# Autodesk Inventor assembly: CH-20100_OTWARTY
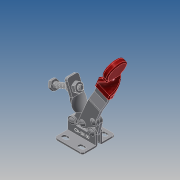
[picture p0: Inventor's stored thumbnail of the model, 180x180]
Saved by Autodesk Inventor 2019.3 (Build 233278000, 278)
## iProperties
Company: Î¢ÈíÖÐ¹ú
Created: 2012-09
Part Number: CH-20100_OTWARTY
Material: Ogólny
Description: STEP AP203
Document SubType Name: Assembly
Designer: CADENGINEERING4
Sending System: SolidWorks 2010
Preprocessor: SwSTEP 2.0
Title: CH-20100.STEP
Author: Î¢ÈíÓÃ»§
Revision Number: ÈÎºÎ
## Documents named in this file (10)
- E:\STRONA\Horizontal toggle clamp\CH-20100\CH-20100_OTWARTY.iam
- E:\STRONA\Horizontal toggle clamp\CH-20100\CH-20100-03 HANDLE.ipt
- E:\STRONA\Horizontal toggle clamp\CH-20100\CH-20100-08.ipt
- E:\STRONA\Horizontal toggle clamp\CH-20100\CH-20100-06.ipt
- E:\STRONA\Horizontal toggle clamp\CH-20100\CH-SA-042507 SPINDLE SUPPLIED.ipt
- E:\STRONA\Horizontal toggle clamp\CH-20100\CH-20100-02 SOLID BAR.ipt
- E:\STRONA\Horizontal toggle clamp\CH-20100\CH-20100-05.ipt
- E:\STRONA\Horizontal toggle clamp\CH-20100\M4 Nut.ipt
- E:\STRONA\Horizontal toggle clamp\CH-20100\CH-20100-01 FLANGED BASE.ipt
- E:\STRONA\Horizontal toggle clamp\CH-20100\CH-20100-04 CONNECTING-PLATE.ipt
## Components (12 placed, 12 different names)
1. CH-20100-03 HANDLE_1 — Zestawiające:1, Zestawiające:2, Zestawiające:3, Zestawiające:23, Zestawiające:24, Zestawiające:25, Zestawiające:26, Zestawiające:27, Przejściowe:1
2. CH-20100-08_2 — Zestawiające:22, Zestawiające:27
3. CH-20100-06_3 — Zestawiające:11, Zestawiające:12
4. CH-SA-042507 SPINDLE SUPPLIED_4 — Równoległe:1, Zestawiające:4, Zestawiające:5, Zestawiające:8
5. CH-20100-02 SOLID BAR_5 — Zestawiające:6, Zestawiające:7, Zestawiające:8, Zestawiające:15, Zestawiające:16, Zestawiające:22, Zestawiające:23, Zestawiające:24
6. CH-20100-05_6 — Zestawiające:1, Zestawiające:2, Zestawiające:3
7. M4 Nut_7 — Równoległe:1, Zestawiające:4, Zestawiające:7
8. CH-20100-01 FLANGED BASE_8 — Zestawiające:9, Zestawiające:10, Zestawiające:11, Zestawiające:12, Zestawiające:15, Zestawiające:16, Zestawiające:17, Zestawiające:18, Przejściowe:1
9. M4 Nut_9 — Zestawiające:5, Zestawiające:6
10. CH-20100-08_10 — Zestawiające:19, Zestawiające:26
11. CH-20100-06_11 — Zestawiające:17, Zestawiające:18
12. CH-20100-04 CONNECTING-PLATE_12 — Zestawiające:9, Zestawiające:10, Zestawiające:19, Zestawiające:25
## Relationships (25: Mate 23, Flush 1, Transitional 1)
- Zestawiające:1 [Mate]: CH-20100-03 HANDLE_1 ↔ CH-20100-05_6
- Zestawiające:2 [Mate]: CH-20100-03 HANDLE_1 ↔ CH-20100-05_6
- Zestawiające:3 [Mate]: CH-20100-03 HANDLE_1 ↔ CH-20100-05_6
- Równoległe:1 [Flush]: CH-SA-042507 SPINDLE SUPPLIED_4 ↔ M4 Nut_7
- Zestawiające:4 [Mate]: CH-SA-042507 SPINDLE SUPPLIED_4 ↔ M4 Nut_7
- Zestawiające:5 [Mate]: CH-SA-042507 SPINDLE SUPPLIED_4 ↔ M4 Nut_9
- Zestawiające:6 [Mate]: CH-20100-02 SOLID BAR_5 ↔ M4 Nut_9
- Zestawiające:7 [Mate]: CH-20100-02 SOLID BAR_5 ↔ M4 Nut_7
- Zestawiające:8 [Mate]: CH-SA-042507 SPINDLE SUPPLIED_4 ↔ CH-20100-02 SOLID BAR_5
- Zestawiające:9 [Mate]: CH-20100-01 FLANGED BASE_8 ↔ CH-20100-04 CONNECTING-PLATE_12
- Zestawiające:10 [Mate]: CH-20100-01 FLANGED BASE_8 ↔ CH-20100-04 CONNECTING-PLATE_12
- Zestawiające:11 [Mate]: CH-20100-06_3 ↔ CH-20100-01 FLANGED BASE_8
- Zestawiające:12 [Mate]: CH-20100-06_3 ↔ CH-20100-01 FLANGED BASE_8
- Zestawiające:15 [Mate]: CH-20100-02 SOLID BAR_5 ↔ CH-20100-01 FLANGED BASE_8
- Zestawiające:16 [Mate]: CH-20100-02 SOLID BAR_5 ↔ CH-20100-01 FLANGED BASE_8
- Zestawiające:17 [Mate]: CH-20100-01 FLANGED BASE_8 ↔ CH-20100-06_11
- Zestawiające:18 [Mate]: CH-20100-01 FLANGED BASE_8 ↔ CH-20100-06_11
- Zestawiające:19 [Mate]: CH-20100-08_10 ↔ CH-20100-04 CONNECTING-PLATE_12
- Zestawiające:22 [Mate]: CH-20100-08_2 ↔ CH-20100-02 SOLID BAR_5
- Zestawiające:23 [Mate]: CH-20100-03 HANDLE_1 ↔ CH-20100-02 SOLID BAR_5
- Zestawiające:24 [Mate]: CH-20100-03 HANDLE_1 ↔ CH-20100-02 SOLID BAR_5
- Zestawiające:25 [Mate]: CH-20100-03 HANDLE_1 ↔ CH-20100-04 CONNECTING-PLATE_12
- Zestawiające:26 [Mate]: CH-20100-03 HANDLE_1 ↔ CH-20100-08_10
- Zestawiające:27 [Mate]: CH-20100-03 HANDLE_1 ↔ CH-20100-08_2
- Przejściowe:1 [Transitional]: CH-20100-03 HANDLE_1 ↔ CH-20100-01 FLANGED BASE_8
